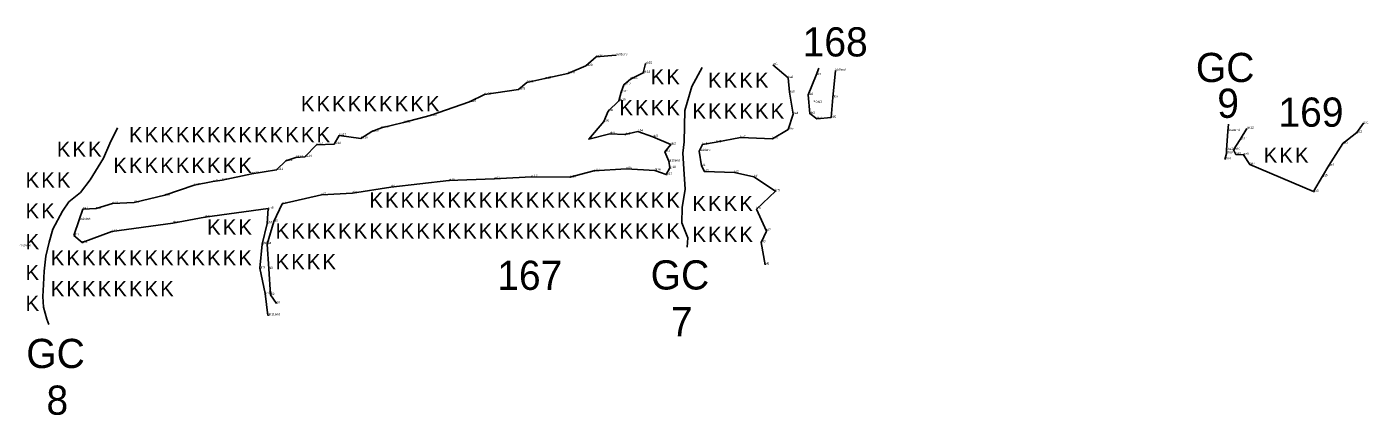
# Model space of a CAD drawing. Extents: x 2072529 to 2268812, y 436423 to 470008.
# Drawn here: x 2186031 to 2189035, y 452943 to 453813 of the extents above; entities that cross this region are included whole.
import ezdxf

# ---------------------------------------------------------------- set-up
doc = ezdxf.new("R2010")
doc.units = 0
for name, color, linetype in [('Old_Level_10', 7, 'Continuous'), ('Old_Level_20', 7, 'Continuous'), ('Old_Level_52', 7, 'Continuous'), ('Old_Level_55', 7, 'Continuous'), ('Old_Level_60', 7, 'Continuous'), ('Old_Level_62', 7, 'Continuous')]:
    doc.layers.add(name, color=color, linetype=linetype)

msp = doc.modelspace()

# ---------------------------------------------------------------- linework, layer by layer
at = {"layer": 'Old_Level_10'}
for points in [[(2187543.284, 453721.892), (2187520.317, 453678.991), (2187504.184, 453625.175), (2187502.839, 453555.215), (2187500.15, 453529.653), (2187502.839, 453482.564), (2187505.528, 453448.93), (2187498.806, 453408.568), (2187497.461, 453373.588), (2187510.906, 453339.953), (2187509.434, 453319.334)], [(2187804.423, 453720.036), (2187798.633, 453704.489), (2187780.274, 453660.113), (2187784.056, 453618.252), (2187799.798, 453606.348), (2187832.106, 453609.419), (2187836.017, 453654.524), (2187841.511, 453714.555)], [(2186233.732, 453586.241), (2186216.936, 453551.333), (2186202.724, 453519.011), (2186173.008, 453469.882), (2186151.045, 453441.439), (2186125.205, 453420.753), (2186110.993, 453400.067), (2186089.03, 453359.987), (2186081.278, 453330.251), (2186073.526, 453299.222), (2186069.65, 453265.608), (2186068.358, 453235.871), (2186067.066, 453208.721), (2186068.358, 453185.449), (2186076.11, 453158.299), (2186079.986, 453146.663)], [(2188721.599, 453594.426), (2188720.48, 453579.261), (2188717.085, 453536.9), (2188717.597, 453529.275), (2188713.376, 453515.784)]]:
    msp.add_lwpolyline(points, dxfattribs=at)
at = {"layer": 'Old_Level_20'}
for p, q in [((2187349.64, 453749.057), (2187349.64, 453749.057)), ((2187282.557, 453724.998), (2187282.557, 453724.998)), ((2187305.802, 453745.488), (2187305.802, 453745.488)), ((2187416.147, 453730.275), (2187416.147, 453730.275)), ((2187701.149, 453727.916), (2187701.149, 453727.916)), ((2187150.61, 453688.322), (2187150.61, 453688.322)), ((2187190.778, 453696.738), (2187190.778, 453696.738)), ((2187242.748, 453708.285), (2187242.748, 453708.285)), ((2187382.847, 453695.75), (2187382.847, 453695.75)), ((2187411.24, 453709.911), (2187411.24, 453709.911)), ((2187735.663, 453698.145), (2187735.663, 453698.145)), ((2187798.633, 453704.489), (2187798.633, 453704.489)), ((2187841.511, 453714.555), (2187841.511, 453714.555)), ((2187055.94, 453660.978), (2187055.94, 453660.978)), ((2187131.666, 453672.34), (2187131.666, 453672.34)), ((2187362.137, 453666.491), (2187362.137, 453666.491)), ((2187368.195, 453682.935), (2187368.195, 453682.935)), ((2187738.653, 453666.086), (2187738.653, 453666.086)), ((2187780.274, 453660.113), (2187780.274, 453660.113)), ((2187022.204, 453644.423), (2187022.204, 453644.423)), ((2187356.652, 453647.285), (2187356.652, 453647.285)), ((2187836.017, 453654.524), (2187836.017, 453654.524)), ((2186874.856, 453598.822), (2186874.856, 453598.822)), ((2186933.879, 453613.882), (2186933.879, 453613.882)), ((2187323.383, 453600.643), (2187323.383, 453600.643)), ((2187332.482, 453623.937), (2187332.482, 453623.937)), ((2187746.902, 453617.39), (2187746.902, 453617.39)), ((2187784.056, 453618.252), (2187784.056, 453618.252)), ((2187799.798, 453606.348), (2187799.798, 453606.348)), ((2187832.106, 453609.419), (2187832.106, 453609.419)), ((2186730.555, 453569.739), (2186730.555, 453569.739)), ((2186803.26, 453578.018), (2186803.26, 453578.018)), ((2186825.246, 453586.599), (2186825.246, 453586.599)), ((2187336.614, 453573.273), (2187336.614, 453573.273)), ((2187370.216, 453571.276), (2187370.216, 453571.276)), ((2187399.562, 453578.387), (2187399.562, 453578.387)), ((2187735.915, 453582.996), (2187735.915, 453582.996)), ((2188720.48, 453579.261), (2188720.48, 453579.261)), ((2188762.938, 453584.984), (2188762.938, 453584.984)), ((2189009.508, 453575.978), (2189009.508, 453575.978)), ((2189023.785, 453596.637), (2189023.785, 453596.637)), ((2186679.637, 453548.238), (2186679.637, 453548.238)), ((2186719.432, 453550.219), (2186719.432, 453550.219)), ((2186779.021, 453562.898), (2186779.021, 453562.898)), ((2187289.474, 453561.316), (2187289.474, 453561.316)), ((2187432.564, 453566.228), (2187432.564, 453566.228)), ((2187472.968, 453549.136), (2187472.968, 453549.136)), ((2187543.694, 453549.038), (2187543.694, 453549.038)), ((2187574.631, 453554.288), (2187574.631, 453554.288)), ((2187628.907, 453564.593), (2187628.907, 453564.593)), ((2187700.966, 453562.06), (2187700.966, 453562.06)), ((2188748.231, 453560.477), (2188748.231, 453560.477)), ((2188977.903, 453551.479), (2188977.903, 453551.479)), ((2186610.658, 453512.334), (2186610.658, 453512.334)), ((2186633.621, 453520.198), (2186633.621, 453520.198)), ((2186653.53, 453521.44), (2186653.53, 453521.44)), ((2187459.488, 453533.034), (2187459.488, 453533.034)), ((2187468.817, 453511.584), (2187468.817, 453511.584)), ((2187536.258, 453534.552), (2187536.258, 453534.552)), ((2188713.376, 453515.784), (2188713.376, 453515.784)), ((2188717.085, 453536.9), (2188717.085, 453536.9)), ((2188717.597, 453529.275), (2188717.597, 453529.275)), ((2188732.898, 453537.355), (2188732.898, 453537.355)), ((2188738.376, 453527.03), (2188738.376, 453527.03)), ((2188755.635, 453526.336), (2188755.635, 453526.336)), ((2186534.873, 453483.93), (2186534.873, 453483.93)), ((2186589.976, 453492.334), (2186589.976, 453492.334)), ((2187301.034, 453490.02), (2187301.034, 453490.02)), ((2187372.892, 453494.832), (2187372.892, 453494.832)), ((2187437.132, 453491.209), (2187437.132, 453491.209)), ((2187462.846, 453481.824), (2187462.846, 453481.824)), ((2187471.15, 453496.667), (2187471.15, 453496.667)), ((2187541.473, 453501.213), (2187541.473, 453501.213)), ((2187548.154, 453488.43), (2187548.154, 453488.43)), ((2187615.392, 453486.283), (2187615.392, 453486.283)), ((2188769.375, 453504.522), (2188769.375, 453504.522)), ((2188932.319, 453478.211), (2188932.319, 453478.211)), ((2188946.641, 453501.972), (2188946.641, 453501.972)), ((2186405.985, 453458.029), (2186405.985, 453458.029)), ((2186447.189, 453466.196), (2186447.189, 453466.196)), ((2186468.717, 453469.48), (2186468.717, 453469.48)), ((2186846.292, 453453.964), (2186846.292, 453453.964)), ((2186976.125, 453468.399), (2186976.125, 453468.399)), ((2187077.296, 453472.275), (2187077.296, 453472.275)), ((2187161.358, 453477.075), (2187161.358, 453477.075)), ((2187247.26, 453476.048), (2187247.26, 453476.048)), ((2187659.175, 453476.658), (2187659.175, 453476.658)), ((2186271.516, 453419.433), (2186271.516, 453419.433)), ((2186339.881, 453435.535), (2186339.881, 453435.535)), ((2186691.238, 453436.803), (2186691.238, 453436.803)), ((2186760.267, 453440.342), (2186760.267, 453440.342)), ((2187707.566, 453444.732), (2187707.566, 453444.732)), ((2188912.305, 453443.799), (2188912.305, 453443.799)), ((2186156.472, 453404.68), (2186156.472, 453404.68)), ((2186186.237, 453405.632), (2186186.237, 453405.632)), ((2186223.086, 453417.017), (2186223.086, 453417.017)), ((2186571.749, 453405.618), (2186571.749, 453405.618)), ((2186603.126, 453416.607), (2186603.126, 453416.607)), ((2187665.019, 453404.519), (2187665.019, 453404.519)), ((2186148.193, 453380.572), (2186148.193, 453380.572)), ((2186357.809, 453373.308), (2186357.809, 453373.308)), ((2186429.472, 453386.364), (2186429.472, 453386.364)), ((2186568.889, 453372.663), (2186568.889, 453372.663)), ((2186583.915, 453376.704), (2186583.915, 453376.704)), ((2186136.415, 453345.7), (2186136.415, 453345.7)), ((2186155.013, 453329.547), (2186155.013, 453329.547)), ((2186221.662, 453354.394), (2186221.662, 453354.394)), ((2187675.244, 453330.234), (2187675.244, 453330.234)), ((2187687.057, 453355.603), (2187687.057, 453355.603)), ((2186558.07, 453326.449), (2186558.07, 453326.449)), ((2186569.125, 453326.285), (2186569.125, 453326.285)), ((2186552.907, 453272.263), (2186552.907, 453272.263)), ((2186572.644, 453270.727), (2186572.644, 453270.727)), ((2187683.99, 453280.142), (2187683.99, 453280.142)), ((2186565.031, 453215.476), (2186565.031, 453215.476)), ((2186576.369, 453212.419), (2186576.369, 453212.419)), ((2186590.171, 453193.442), (2186590.171, 453193.442)), ((2186570.767, 453166.699), (2186570.767, 453166.699))]:
    msp.add_line(p, q, dxfattribs=at)
at = {"layer": 'Old_Level_52'}
for points in [[(2186136.415, 453345.7), (2186148.193, 453380.572), (2186156.472, 453404.68), (2186186.237, 453405.632), (2186223.086, 453417.017), (2186271.516, 453419.433), (2186339.881, 453435.535), (2186405.985, 453458.029), (2186447.189, 453466.196), (2186468.717, 453469.48), (2186534.873, 453483.93), (2186589.976, 453492.334), (2186610.658, 453512.334), (2186633.621, 453520.198), (2186653.53, 453521.44), (2186679.637, 453548.238), (2186719.432, 453550.219), (2186730.555, 453569.739), (2186779.021, 453562.898), (2186803.26, 453578.018), (2186825.246, 453586.599), (2186874.856, 453598.822), (2186933.879, 453613.882), (2187022.204, 453644.423), (2187055.94, 453660.978), (2187131.666, 453672.34), (2187150.61, 453688.322), (2187190.778, 453696.738), (2187242.748, 453708.285), (2187282.557, 453724.998), (2187305.802, 453745.488), (2187349.64, 453749.057)], [(2187468.817, 453511.584), (2187459.488, 453533.034), (2187472.968, 453549.136), (2187432.564, 453566.228), (2187399.562, 453578.387), (2187370.216, 453571.276), (2187336.614, 453573.273), (2187289.474, 453561.316), (2187323.383, 453600.643), (2187332.482, 453623.937), (2187356.652, 453647.285), (2187362.137, 453666.491), (2187368.195, 453682.935), (2187382.847, 453695.75), (2187411.24, 453709.911), (2187416.147, 453730.275)], [(2187701.149, 453727.916), (2187735.663, 453698.145), (2187738.653, 453666.086), (2187746.902, 453617.39), (2187735.915, 453582.996), (2187700.966, 453562.06), (2187628.907, 453564.593), (2187574.631, 453554.288), (2187543.694, 453549.038), (2187536.258, 453534.552), (2187541.473, 453501.213)], [(2188762.938, 453584.984), (2188748.231, 453560.477), (2188732.898, 453537.355), (2188738.376, 453527.03), (2188755.635, 453526.336), (2188769.375, 453504.522), (2188912.305, 453443.799), (2188932.319, 453478.211), (2188946.641, 453501.972), (2188977.903, 453551.479), (2189009.508, 453575.978), (2189023.785, 453596.637)], [(2186590.171, 453193.442), (2186576.369, 453212.419), (2186572.644, 453270.727), (2186569.125, 453326.285), (2186583.915, 453376.704), (2186603.126, 453416.607), (2186691.238, 453436.803), (2186760.267, 453440.342), (2186846.292, 453453.964), (2186976.125, 453468.399), (2187077.296, 453472.275), (2187161.358, 453477.075), (2187247.26, 453476.048), (2187301.034, 453490.02), (2187372.892, 453494.832), (2187437.132, 453491.209), (2187462.846, 453481.824), (2187471.15, 453496.667), (2187468.817, 453511.584)], [(2187541.473, 453501.213), (2187548.154, 453488.43), (2187615.392, 453486.283), (2187659.175, 453476.658), (2187707.566, 453444.732), (2187665.019, 453404.519), (2187687.057, 453355.603), (2187675.244, 453330.234), (2187683.99, 453280.142)], [(2186136.415, 453345.7), (2186155.013, 453329.547), (2186221.662, 453354.394), (2186357.809, 453373.308), (2186429.472, 453386.364), (2186571.749, 453405.618), (2186568.889, 453372.663), (2186558.07, 453326.449), (2186552.907, 453272.263), (2186565.031, 453215.476), (2186570.767, 453166.699)]]:
    msp.add_lwpolyline(points, dxfattribs=at)

# ---------------------------------------------------------------- texts
at = {"layer": 'Old_Level_55'}
for p in [(2187427.989, 453683.81), (2187462.989, 453683.81), (2187556.462, 453676.289), (2187591.462, 453676.289), (2187626.462, 453676.289), (2187661.462, 453676.289), (2186644.718, 453623.423), (2186679.718, 453623.423), (2186714.718, 453623.423), (2186749.718, 453623.423), (2186784.718, 453623.423), (2186819.718, 453623.423), (2186854.718, 453623.423), (2186889.718, 453623.423), (2186924.718, 453623.423), (2187357.989, 453614.81), (2187392.989, 453614.81), (2187427.989, 453614.81), (2187462.989, 453614.81), (2187521.462, 453607.289), (2187556.462, 453607.289), (2187591.462, 453607.289), (2187626.462, 453607.289), (2187661.462, 453607.289), (2187696.462, 453607.289), (2186259.718, 453554.423), (2186294.718, 453554.423), (2186329.718, 453554.423), (2186364.718, 453554.423), (2186399.718, 453554.423), (2186434.718, 453554.423), (2186469.718, 453554.423), (2186504.718, 453554.423), (2186539.718, 453554.423), (2186574.718, 453554.423), (2186609.718, 453554.423), (2186644.718, 453554.423), (2186679.718, 453554.423), (2186098.247, 453521.881), (2186133.247, 453521.881), (2186168.247, 453521.881), (2188800.867, 453508.412), (2188835.867, 453508.412), (2188870.867, 453508.412), (2186224.718, 453485.423), (2186259.718, 453485.423), (2186294.718, 453485.423), (2186329.718, 453485.423), (2186364.718, 453485.423), (2186399.718, 453485.423), (2186434.718, 453485.423), (2186469.718, 453485.423), (2186504.718, 453485.423), (2186028.247, 453452.881), (2186063.247, 453452.881), (2186098.247, 453452.881), (2186028.247, 453383.881), (2186063.247, 453383.881), (2186797.989, 453407.81), (2186832.989, 453407.81), (2186867.989, 453407.81), (2186902.989, 453407.81), (2186937.989, 453407.81), (2186972.989, 453407.81), (2187007.989, 453407.81), (2187042.989, 453407.81), (2187077.989, 453407.81), (2187112.989, 453407.81), (2187147.989, 453407.81), (2187182.989, 453407.81), (2187217.989, 453407.81), (2187252.989, 453407.81), (2187287.989, 453407.81), (2187322.989, 453407.81), (2187357.989, 453407.81), (2187392.989, 453407.81), (2187427.989, 453407.81), (2187462.989, 453407.81), (2187521.462, 453400.289), (2187556.462, 453400.289), (2187591.462, 453400.289), (2187626.462, 453400.289), (2186434.718, 453347.423), (2186469.718, 453347.423), (2186504.718, 453347.423), (2186587.989, 453338.81), (2186622.989, 453338.81), (2186657.989, 453338.81), (2186692.989, 453338.81), (2186727.989, 453338.81), (2186762.989, 453338.81), (2186797.989, 453338.81), (2186832.989, 453338.81), (2186867.989, 453338.81), (2186902.989, 453338.81), (2186937.989, 453338.81), (2186972.989, 453338.81), (2187007.989, 453338.81), (2187042.989, 453338.81), (2187077.989, 453338.81), (2187112.989, 453338.81), (2187147.989, 453338.81), (2187182.989, 453338.81), (2187217.989, 453338.81), (2187252.989, 453338.81), (2187287.989, 453338.81), (2187322.989, 453338.81), (2187357.989, 453338.81), (2187392.989, 453338.81), (2187427.989, 453338.81), (2187462.989, 453338.81), (2187521.462, 453331.289), (2187556.462, 453331.289), (2187591.462, 453331.289), (2187626.462, 453331.289), (2186028.247, 453314.881), (2186084.718, 453278.423), (2186119.718, 453278.423), (2186154.718, 453278.423), (2186189.718, 453278.423), (2186224.718, 453278.423), (2186259.718, 453278.423), (2186294.718, 453278.423), (2186329.718, 453278.423), (2186364.718, 453278.423), (2186399.718, 453278.423), (2186434.718, 453278.423), (2186469.718, 453278.423), (2186504.718, 453278.423), (2186587.989, 453269.81), (2186622.989, 453269.81), (2186657.989, 453269.81), (2186692.989, 453269.81), (2186028.247, 453245.881), (2186084.718, 453209.423), (2186119.718, 453209.423), (2186154.718, 453209.423), (2186189.718, 453209.423), (2186224.718, 453209.423), (2186259.718, 453209.423), (2186294.718, 453209.423), (2186329.718, 453209.423), (2186028.247, 453176.881)]:
    msp.add_text('K', height=34, dxfattribs=at).set_placement(p)
at = {"layer": 'Old_Level_60'}
for s, p in [('pa30', (2187305.802, 453745.488)), ('pa31end', (2187349.64, 453749.057)), ('pa29', (2187282.557, 453724.998)), ('gb15', (2187416.147, 453730.275)), ('ha1', (2187701.149, 453727.916)), ('hb7end', (2187841.511, 453714.555)), ('pa26', (2187150.61, 453688.322)), ('pa27', (2187190.778, 453696.738)), ('pa28', (2187242.748, 453708.285)), ('gb12', (2187368.195, 453682.935)), ('gb13', (2187382.847, 453695.75)), ('gb14', (2187411.24, 453709.911)), ('ha2', (2187735.663, 453698.145)), ('hb1', (2187798.633, 453704.489)), ('pa24', (2187055.94, 453660.978)), ('pa25', (2187131.666, 453672.34)), ('gb11', (2187362.137, 453666.491)), ('ha3', (2187738.653, 453666.086)), ('hb2', (2187780.274, 453660.113)), ('hb6', (2187836.017, 453654.524)), ('pa23', (2187022.204, 453644.423)), ('gb9', (2187332.482, 453623.937)), ('gb10', (2187356.652, 453647.285)), ('POND', (2187792.041, 453642.335)), ('pa21', (2186874.856, 453598.822)), ('pa22', (2186933.879, 453613.882)), ('gb8', (2187323.383, 453600.643)), ('ha4', (2187746.902, 453617.39)), ('hb3', (2187784.056, 453618.252)), ('hb4', (2187799.798, 453606.348)), ('hb5', (2187832.106, 453609.419)), ('ga1', (2189023.785, 453596.637)), ('pa17', (2186730.555, 453569.739)), ('pa18', (2186779.021, 453562.898)), ('pa19', (2186803.26, 453578.018)), ('pa20', (2186825.246, 453586.599)), ('gb6', (2187336.614, 453573.273)), ('gb5', (2187370.216, 453571.276)), ('gb4', (2187399.562, 453578.387)), ('gb3', (2187432.564, 453566.228)), ('ha7', (2187628.907, 453564.593)), ('ha5', (2187735.915, 453582.996)), ('sha4end', (2188720.48, 453579.261)), ('ga12', (2188762.938, 453584.984)), ('ga2', (2189009.508, 453575.978)), ('pa15', (2186679.637, 453548.238)), ('pa16', (2186719.432, 453550.219)), ('gb7', (2187289.474, 453561.316)), ('gb1', (2187459.488, 453533.034)), ('gb2', (2187472.968, 453549.136)), ('ha10end', (2187536.258, 453534.552)), ('ha9', (2187543.694, 453549.038)), ('ha8', (2187574.631, 453554.288)), ('ha6', (2187700.966, 453562.06)), ('sha3', (2188717.085, 453536.9)), ('ga10', (2188732.898, 453537.355)), ('ga11', (2188748.231, 453560.477)), ('ga3', (2188977.903, 453551.479)), ('pa12', (2186610.658, 453512.334)), ('pa13', (2186633.621, 453520.198)), ('pa14', (2186653.53, 453521.44)), ('gi19end', (2187468.817, 453511.584)), ('sha1', (2188713.376, 453515.784)), ('sha2', (2188717.597, 453529.275)), ('ga9', (2188738.376, 453527.03)), ('ga8', (2188755.635, 453526.336)), ('ga7', (2188769.375, 453504.522)), ('pa10', (2186534.873, 453483.93)), ('pa11', (2186589.976, 453492.334)), ('gi12', (2187161.358, 453477.075)), ('gi13', (2187247.26, 453476.048)), ('gi14', (2187301.034, 453490.02)), ('gi15', (2187372.892, 453494.832)), ('gi16', (2187437.132, 453491.209)), ('gi17', (2187462.846, 453481.824)), ('gi18', (2187471.15, 453496.667)), ('hf1', (2187541.473, 453501.213)), ('hf2', (2187548.154, 453488.43)), ('hf3', (2187615.392, 453486.283)), ('hf4', (2187659.175, 453476.658)), ('ga5', (2188932.319, 453478.211)), ('ga4', (2188946.641, 453501.972)), ('pa7', (2186405.985, 453458.029)), ('pa8', (2186447.189, 453466.196)), ('pa9', (2186468.717, 453469.48)), ('gi9', (2186846.292, 453453.964)), ('gi10', (2186976.125, 453468.399)), ('gi11', (2187077.296, 453472.275)), ('hf5', (2187707.566, 453444.732)), ('ga6', (2188912.305, 453443.799)), ('pa4', (2186223.086, 453417.017)), ('pa5', (2186271.516, 453419.433)), ('pa6', (2186339.881, 453435.535)), ('gi6', (2186603.126, 453416.607)), ('gi7', (2186691.238, 453436.803)), ('gi8', (2186760.267, 453440.342)), ('pa2', (2186156.472, 453404.68)), ('pa3', (2186186.237, 453405.632)), ('gh5', (2186429.472, 453386.364)), ('gh6', (2186571.749, 453405.618)), ('hf6', (2187665.019, 453404.519)), ('pa1start', (2186148.193, 453380.572)), ('gh3', (2186221.662, 453354.394)), ('gh4', (2186357.809, 453373.308)), ('gh7', (2186568.889, 453372.663)), ('gi5', (2186583.915, 453376.704)), ('hf7', (2187687.057, 453355.603)), ('gh1', (2186136.415, 453345.7)), ('gh2', (2186155.013, 453329.547)), ('gh8', (2186558.07, 453326.449)), ('gi4', (2186569.125, 453326.285)), ('hf8', (2187675.244, 453330.234)), ('he32end', (2186014.23, 453321.091)), ('gh9', (2186552.907, 453272.263)), ('gi3', (2186572.644, 453270.727)), ('hf9', (2187683.99, 453280.142)), ('gh10', (2186565.031, 453215.476)), ('gi2', (2186576.369, 453212.419)), ('gi1', (2186590.171, 453193.442)), ('gh11end', (2186570.767, 453166.699))]:
    msp.add_text(s, height=5, dxfattribs=at).set_placement(p)
at = {"layer": 'Old_Level_62'}
for s, p in [('168', (2187768.263, 453746.286)), ('GC', (2188648.756, 453688.989)), ('9', (2188696.737, 453608.89)), ('169', (2188833.601, 453589.063)), ('167', (2187084.361, 453223.805)), ('GC', (2187427.967, 453224.645)), ('7', (2187473.127, 453120.101)), ('GC', (2186029.855, 453048.866)), ('8', (2186075.016, 452944.322))]:
    msp.add_text(s, height=65.34, dxfattribs=at).set_placement(p)

doc.saveas('drawing.dxf')
